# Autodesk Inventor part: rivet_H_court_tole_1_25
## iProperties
Created: 2011-01
Part Number: rivet_H_court_tole_1_25
Document SubType Name: Modeling
Designer: eric
Density: 1 g/cm^3
Mass: 0.0765391 g
Surface Area: 1.79462 cm^2
Volume: 0.0765391 cm^3
Author: eric
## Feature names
1. Base1
